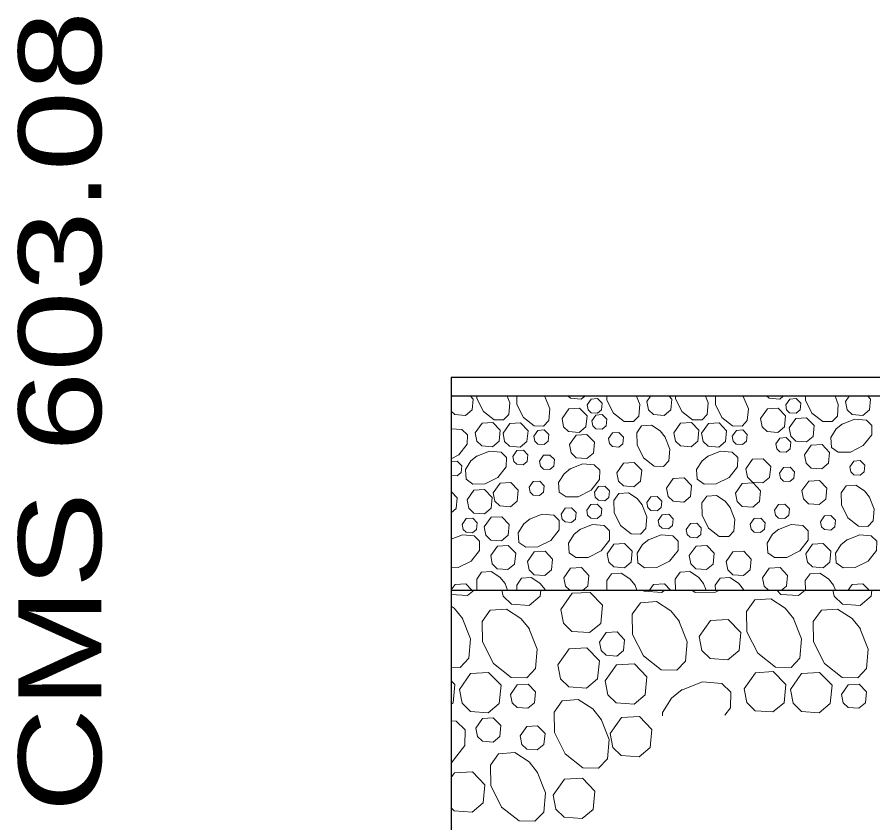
# Model space of a CAD drawing. Extents: x 1083.1 to 1117.1, y 697.4 to 741.4.
# Drawn here: x 1098.097 to 1099.707, y 705.8 to 707.316 of the extents above; entities that cross this region are included whole.
import ezdxf
from ezdxf.enums import TextEntityAlignment as Align

# ---------------------------------------------------------------- set-up
doc = ezdxf.new("R2010")
doc.units = 0
doc.header["$LTSCALE"] = 0.062
doc.layers.add('1', color=7, linetype='Continuous', lineweight=13)

msp = doc.modelspace()

# ---------------------------------------------------------------- linework, layer by layer
at = {"layer": '1', "lineweight": 25}
for p, q in [((1101.19942, 706.63767), (1098.91383, 706.63767)), ((1098.91383, 706.63767), (1098.91383, 705.41058)), ((1098.91383, 706.23775), (1101.19942, 706.23775))]:
    msp.add_line(p, q, dxfattribs=at)
at = {"layer": '1'}
for p, q in [((1098.91383, 706.60092), (1098.91525, 706.60292)), ((1099.08917, 706.60292), (1099.09025, 706.6015)), ((1099.28175, 706.593), (1099.28875, 706.60292)), ((1099.46275, 706.60292), (1099.46383, 706.6015)), ((1099.65533, 706.593), (1099.66233, 706.60292)), ((1099.01442, 706.2515), (1099.01983, 706.23775)), ((1099.25892, 706.24842), (1099.26317, 706.23775)), ((1099.38792, 706.2515), (1099.39342, 706.23775)), ((1099.6325, 706.24842), (1099.63675, 706.23775)), ((1099.08958, 706.24), (1099.09058, 706.23775)), ((1099.46317, 706.24), (1099.46417, 706.23775))]:
    msp.add_line(p, q, dxfattribs=at)
at = {"layer": '1', "lineweight": 25}
msp.add_lwpolyline([(1101.19942, 706.23775), (1101.19942, 706.63767), (1101.19942, 706.60292), (1098.91383, 706.60292)], dxfattribs=at)
at = {"layer": '1'}
for points in [[(1098.95008, 706.60292), (1098.95525, 706.5975), (1098.95317, 706.57708), (1098.94067, 706.56667), (1098.92067, 706.56808), (1098.91383, 706.57483)], [(1099.01883, 706.60292), (1099.02375, 706.59025), (1099.02192, 706.56842), (1099.01208, 706.55808), (1098.99433, 706.55833), (1098.97425, 706.57408), (1098.96208, 706.59842), (1098.962, 706.60292)], [(1099.08958, 706.60242), (1099.09908, 706.57875), (1099.09717, 706.55683), (1099.08733, 706.54658), (1099.06967, 706.54692), (1099.0495, 706.56258), (1099.03733, 706.58692), (1099.03708, 706.60292)], [(1099.16483, 706.60292), (1099.15825, 706.59742), (1099.13817, 706.59883), (1099.134, 706.60292)], [(1099.26217, 706.60292), (1099.26833, 706.58717), (1099.2665, 706.56533), (1099.25667, 706.555), (1099.23892, 706.55525), (1099.21875, 706.571), (1099.20667, 706.59533), (1099.2065, 706.60292)], [(1099.32367, 706.60292), (1099.32875, 706.5975), (1099.32683, 706.57708), (1099.31425, 706.56667), (1099.29425, 706.56808), (1099.28475, 706.57725), (1099.28183, 706.593)], [(1099.39233, 706.60292), (1099.39733, 706.59025), (1099.3955, 706.56842), (1099.38567, 706.55808), (1099.36792, 706.55833), (1099.34783, 706.57408), (1099.33567, 706.59842), (1099.33558, 706.60292)], [(1099.46317, 706.60242), (1099.47267, 706.57875), (1099.47075, 706.55683), (1099.46083, 706.54658), (1099.44317, 706.54692), (1099.42308, 706.56258), (1099.41092, 706.58692), (1099.41067, 706.60292)], [(1099.53842, 706.60292), (1099.53183, 706.59742), (1099.51175, 706.59883), (1099.50758, 706.60292)], [(1099.63575, 706.60292), (1099.64192, 706.58717), (1099.64008, 706.56533), (1099.63025, 706.555), (1099.6125, 706.55525), (1099.59233, 706.571), (1099.58025, 706.59533), (1099.58008, 706.60292)], [(1099.69725, 706.60292), (1099.70233, 706.5975), (1099.70033, 706.57708), (1099.68783, 706.56667), (1099.66783, 706.56808), (1099.65842, 706.57725), (1099.65533, 706.593)], [(1099.64917, 706.55008), (1099.67292, 706.5595), (1099.69467, 706.55767), (1099.70508, 706.54783), (1099.70467, 706.53008), (1099.68892, 706.51), (1099.66467, 706.49775), (1099.64175, 706.49733), (1099.62883, 706.50658), (1099.62758, 706.52483), (1099.63808, 706.54108), (1099.65008, 706.55075)], [(1098.91383, 706.54167), (1098.93367, 706.53992), (1098.94408, 706.53008), (1098.94375, 706.51242), (1098.928, 706.49225), (1098.91383, 706.48517)], [(1099.3155, 706.52675), (1099.325, 706.50308), (1099.32308, 706.48117), (1099.31325, 706.47083), (1099.29558, 706.47117), (1099.27542, 706.48692), (1099.26333, 706.51125), (1099.26292, 706.53417), (1099.272, 706.547), (1099.29025, 706.54833), (1099.30667, 706.53775), (1099.31617, 706.52575)], [(1098.96183, 706.49), (1098.98558, 706.49942), (1099.00742, 706.49758), (1099.01783, 706.48775), (1099.01742, 706.47), (1099.00167, 706.44992), (1098.97733, 706.43767), (1098.9545, 706.43725), (1098.94158, 706.4465), (1098.94033, 706.46475), (1098.95075, 706.481), (1098.96283, 706.49067)], [(1099.39683, 706.49), (1099.42058, 706.49942), (1099.44233, 706.49758), (1099.45275, 706.48775), (1099.45233, 706.47), (1099.43658, 706.44992), (1099.41233, 706.43767), (1099.38942, 706.43725), (1099.3765, 706.4465), (1099.37525, 706.46475), (1099.38575, 706.481), (1099.39775, 706.49067)], [(1098.91383, 706.47967), (1098.92508, 706.48033), (1098.9335, 706.47158), (1098.93225, 706.45933), (1098.92475, 706.453), (1098.91383, 706.45383)], [(1099.13725, 706.466), (1099.16108, 706.47542), (1099.18283, 706.4735), (1099.19325, 706.46367), (1099.19283, 706.446), (1099.17708, 706.42583), (1099.15275, 706.41367), (1099.12992, 706.41325), (1099.117, 706.4225), (1099.11575, 706.44075), (1099.12617, 706.457), (1099.13825, 706.46658)], [(1098.91383, 706.42367), (1098.92525, 706.41175), (1098.92325, 706.39125), (1098.91383, 706.38342)], [(1099.27225, 706.39942), (1099.28175, 706.37567), (1099.27983, 706.35383), (1099.27, 706.34342), (1099.25225, 706.34383), (1099.23217, 706.35958), (1099.22, 706.38392), (1099.21967, 706.40675), (1099.22875, 706.41967), (1099.247, 706.42092), (1099.26342, 706.41042), (1099.27292, 706.39842)], [(1099.7, 706.41383), (1099.70942, 706.39008), (1099.70758, 706.36825), (1099.69775, 706.35783), (1099.68, 706.35825), (1099.65992, 706.374), (1099.64775, 706.39833), (1099.64742, 706.42117), (1099.6565, 706.43408), (1099.67475, 706.43533), (1099.69117, 706.42483), (1099.70067, 706.41283)], [(1099.43808, 706.39458), (1099.4475, 706.37092), (1099.44567, 706.349), (1099.43583, 706.33867), (1099.41808, 706.339), (1099.398, 706.35475), (1099.38583, 706.37908), (1099.3855, 706.402), (1099.39458, 706.41483), (1099.41283, 706.41617), (1099.42917, 706.40558), (1099.43875, 706.39367)], [(1099.06125, 706.37142), (1099.085, 706.38083), (1099.10675, 706.37892), (1099.11708, 706.36908), (1099.11675, 706.35142), (1099.101, 706.33125), (1099.07675, 706.31917), (1099.05383, 706.31875), (1099.04092, 706.32783), (1099.03967, 706.34608), (1099.05017, 706.3625), (1099.06217, 706.372)], [(1099.15575, 706.35192), (1099.1795, 706.36133), (1099.20133, 706.3595), (1099.21175, 706.34958), (1099.21142, 706.33192), (1099.19567, 706.31183), (1099.17133, 706.29958), (1099.14842, 706.29925), (1099.1355, 706.30833), (1099.13433, 706.32658), (1099.14475, 706.343), (1099.15675, 706.35258)], [(1099.52933, 706.35192), (1099.55308, 706.36133), (1099.57492, 706.3595), (1099.58533, 706.34958), (1099.585, 706.33192), (1099.56925, 706.31183), (1099.54492, 706.29958), (1099.522, 706.29925), (1099.50908, 706.30833), (1099.50792, 706.32658), (1099.51833, 706.343), (1099.53033, 706.35258)], [(1098.91383, 706.33375), (1098.935, 706.34208), (1098.95675, 706.34025), (1098.96717, 706.33042), (1098.96683, 706.31267), (1098.95108, 706.29267), (1098.92675, 706.28042), (1098.91383, 706.28017)], [(1099.28475, 706.33275), (1099.30858, 706.34208), (1099.33033, 706.34025), (1099.34075, 706.33042), (1099.34042, 706.31267), (1099.32467, 706.29267), (1099.30025, 706.28042), (1099.27742, 706.28), (1099.2645, 706.28917), (1099.26333, 706.30742), (1099.27375, 706.32375), (1099.28575, 706.33342)], [(1099.65842, 706.33275), (1099.68217, 706.34208), (1099.70392, 706.34025), (1099.71433, 706.33042), (1099.71392, 706.31267), (1099.69817, 706.29267), (1099.67392, 706.28042), (1099.651, 706.28), (1099.63808, 706.28917), (1099.63692, 706.30742), (1099.64733, 706.32375), (1099.65933, 706.33342)], [(1099.20708, 706.3065), (1099.21983, 706.32458), (1099.24, 706.32567), (1099.25417, 706.31108), (1099.25217, 706.29058), (1099.23958, 706.28017), (1099.21958, 706.28167), (1099.21017, 706.29083), (1099.20717, 706.3065)], [(1099.12575, 706.26117), (1099.13842, 706.27925), (1099.15867, 706.28033), (1099.17275, 706.26583), (1099.17075, 706.24533), (1099.16158, 706.23775)], [(1099.49933, 706.26117), (1099.512, 706.27925), (1099.53225, 706.28033), (1099.54633, 706.26583), (1099.54433, 706.24533), (1099.53517, 706.23775)], [(1098.96208, 706.23775), (1098.96167, 706.25892), (1098.97083, 706.27175), (1098.98908, 706.273), (1099.00542, 706.2625), (1099.015, 706.2505)], [(1099.03708, 706.23775), (1099.03692, 706.24733), (1099.04608, 706.26025), (1099.06433, 706.2615), (1099.08067, 706.251), (1099.09025, 706.23908)], [(1099.13683, 706.23775), (1099.12883, 706.2455), (1099.12575, 706.26117)], [(1099.20658, 706.23775), (1099.20625, 706.25583), (1099.21542, 706.26875), (1099.23367, 706.26992), (1099.25, 706.25942), (1099.25958, 706.2475)], [(1099.33567, 706.23775), (1099.33525, 706.25892), (1099.34442, 706.27175), (1099.36267, 706.273), (1099.379, 706.2625), (1099.38858, 706.2505)], [(1099.41067, 706.23775), (1099.4105, 706.24733), (1099.41967, 706.26025), (1099.43792, 706.2615), (1099.45425, 706.251), (1099.46383, 706.23908)], [(1099.51042, 706.23775), (1099.50242, 706.2455), (1099.49933, 706.26117)], [(1099.58017, 706.23775), (1099.57983, 706.25583), (1099.589, 706.26875), (1099.60725, 706.26992), (1099.62358, 706.25942), (1099.63317, 706.2475)], [(1098.91383, 706.23842), (1098.92092, 706.2485), (1098.94108, 706.24967), (1098.95267, 706.23775)], [(1099.28683, 706.23775), (1099.2945, 706.2485), (1099.31467, 706.24967), (1099.32617, 706.23775)], [(1099.66042, 706.23775), (1099.66808, 706.2485), (1099.68825, 706.24967), (1099.69975, 706.23775)], [(1098.95667, 706.23775), (1098.94467, 706.22767), (1098.91383, 706.22992)], [(1099.08225, 706.23775), (1099.08108, 706.22667), (1099.06025, 706.20925), (1099.02692, 706.21167), (1099.01125, 706.22683), (1099.00917, 706.23775)], [(1099.31492, 706.23775), (1099.30992, 706.23358), (1099.2765, 706.236), (1099.27475, 706.23775)], [(1099.41858, 706.23775), (1099.41108, 706.23392), (1099.37292, 706.23333), (1099.36667, 706.23775)], [(1099.57933, 706.23775), (1099.56725, 706.22767), (1099.53392, 706.23008), (1099.526, 706.23775)], [(1099.70483, 706.23775), (1099.70375, 706.22667), (1099.68292, 706.20925), (1099.64958, 706.21167), (1099.63392, 706.22683), (1099.63175, 706.23775)], [(1099.34217, 706.18058), (1099.35783, 706.141), (1099.35467, 706.10467), (1099.33825, 706.08742), (1099.30875, 706.08792), (1099.27525, 706.11425), (1099.255, 706.15475), (1099.25425, 706.19292), (1099.26958, 706.21442), (1099.3, 706.21642), (1099.32717, 706.199), (1099.34317, 706.179)], [(1099.55717, 706.18575), (1099.57275, 706.14617), (1099.56967, 706.10983), (1099.55325, 706.0925), (1099.52375, 706.09308), (1099.49025, 706.11933), (1099.47, 706.15983), (1099.46925, 706.198), (1099.48458, 706.21958), (1099.515, 706.22158), (1099.54217, 706.20417), (1099.55817, 706.18417)], [(1098.91383, 706.20783), (1098.9195, 706.20417), (1098.9355, 706.18417)], [(1099.05992, 706.1665), (1099.07558, 706.12692), (1099.0725, 706.09058), (1099.056, 706.07333), (1099.0265, 706.07383), (1098.993, 706.10017), (1098.97283, 706.14067), (1098.97208, 706.17883), (1098.98733, 706.20033), (1099.01783, 706.20242), (1099.045, 706.18492), (1099.06092, 706.16492)], [(1099.6825, 706.1665), (1099.69825, 706.12692), (1099.69508, 706.09058), (1099.67867, 706.07333), (1099.64917, 706.07383), (1099.61567, 706.10017), (1099.59533, 706.14067), (1099.59475, 706.17883), (1099.61, 706.20033), (1099.64042, 706.20242), (1099.66767, 706.18492), (1099.68358, 706.16492)], [(1098.9345, 706.18575), (1098.95025, 706.14617), (1098.94708, 706.10983), (1098.93067, 706.0925), (1098.91383, 706.09283)], [(1099.46475, 706.05258), (1099.48592, 706.08267), (1099.51967, 706.08467), (1099.54317, 706.06025), (1099.53983, 706.02617), (1099.51892, 706.00883), (1099.48567, 706.01125), (1099.46992, 706.02642), (1099.46475, 706.0525)], [(1099.55175, 706.05125), (1099.57292, 706.08142), (1099.60675, 706.08325), (1099.63025, 706.059), (1099.62683, 706.02483), (1099.606, 706.0075), (1099.57267, 706.00992), (1099.55692, 706.02517), (1099.55183, 706.05125)], [(1098.91383, 706.06725), (1098.92058, 706.06025), (1098.91717, 706.02617), (1098.91383, 706.02333)], [(1099.31142, 706.00142), (1099.311, 706.00767), (1099.32842, 706.03492), (1099.34833, 706.05083)], [(1099.34675, 706.04983), (1099.38633, 706.0655), (1099.42267, 706.06233), (1099.44, 706.04592), (1099.43942, 706.01642), (1099.42875, 706.00275)], [(1099.19492, 705.99633), (1099.21067, 705.95683), (1099.2075, 705.92042), (1099.19108, 705.90317), (1099.16158, 705.90367), (1099.12808, 705.92992), (1099.10775, 705.97042), (1099.10717, 706.00867), (1099.12242, 706.03008), (1099.15283, 706.03217), (1099.18, 706.01467), (1099.196, 705.99475)], [(1098.91383, 705.99242), (1098.92283, 705.99167), (1098.94017, 705.97525), (1098.93958, 705.94575), (1098.91383, 705.91267)], [(1099.07525, 705.8965), (1099.09092, 705.857), (1099.08783, 705.82058), (1099.07133, 705.80333), (1099.04183, 705.80383), (1099.00833, 705.83008), (1098.98817, 705.87058), (1098.98742, 705.90883), (1099.00267, 705.93025), (1099.03317, 705.93233), (1099.06033, 705.91483), (1099.07625, 705.89492)], [(1098.91383, 705.88558), (1098.91992, 705.89433), (1098.95367, 705.89633), (1098.97717, 705.87192), (1098.97383, 705.83783), (1098.95292, 705.8205), (1098.9195, 705.82292), (1098.91383, 705.8285)]]:
    msp.add_lwpolyline(points, dxfattribs=at)
for points in [[(1099.16933, 706.58667), (1099.17692, 706.5975), (1099.18917, 706.59817), (1099.19758, 706.58942), (1099.19633, 706.57717), (1099.18883, 706.57083), (1099.17675, 706.57175), (1099.17117, 706.57725)], [(1099.54292, 706.58667), (1099.5505, 706.5975), (1099.56267, 706.59817), (1099.57117, 706.58942), (1099.56992, 706.57717), (1099.56242, 706.57083), (1099.55033, 706.57175), (1099.54475, 706.57725)], [(1099.12217, 706.561), (1099.13483, 706.579), (1099.15517, 706.58017), (1099.16925, 706.56558), (1099.16717, 706.54508), (1099.15467, 706.53467), (1099.13458, 706.53608), (1099.12525, 706.54525)], [(1099.17817, 706.55658), (1099.18583, 706.56733), (1099.19792, 706.56808), (1099.20642, 706.55933), (1099.20517, 706.54708), (1099.19767, 706.54075), (1099.18567, 706.54167), (1099.18, 706.54717)], [(1099.49575, 706.561), (1099.50842, 706.579), (1099.52867, 706.58017), (1099.54283, 706.56558), (1099.54075, 706.54508), (1099.52817, 706.53467), (1099.50817, 706.53608), (1099.49875, 706.54525)], [(1098.95892, 706.53408), (1098.97167, 706.55217), (1098.99192, 706.55333), (1099.006, 706.53867), (1099.00392, 706.51825), (1098.99142, 706.50775), (1098.9715, 706.50925), (1098.962, 706.51842)], [(1099.01117, 706.53325), (1099.02383, 706.55133), (1099.04417, 706.5525), (1099.05825, 706.53792), (1099.05617, 706.51742), (1099.04367, 706.50708), (1099.02367, 706.5085), (1099.01425, 706.51758)], [(1099.3325, 706.53408), (1099.34517, 706.55217), (1099.3655, 706.55333), (1099.37958, 706.53867), (1099.37758, 706.51825), (1099.365, 706.50775), (1099.34508, 706.50925), (1099.33558, 706.51842)], [(1099.38475, 706.53325), (1099.39742, 706.55133), (1099.41775, 706.5525), (1099.43183, 706.53792), (1099.42975, 706.51742), (1099.41725, 706.50708), (1099.39725, 706.5085), (1099.38783, 706.51758)], [(1099.54933, 706.543), (1099.56208, 706.56108), (1099.58233, 706.56225), (1099.59642, 706.54767), (1099.59433, 706.52717), (1099.58183, 706.51675), (1099.56183, 706.51817), (1099.55242, 706.52733)], [(1099.06892, 706.52775), (1099.07658, 706.5385), (1099.08875, 706.53925), (1099.09717, 706.5305), (1099.09592, 706.51825), (1099.08842, 706.51192), (1099.07642, 706.51283), (1099.07075, 706.51833)], [(1099.20942, 706.52292), (1099.21708, 706.53375), (1099.22917, 706.53442), (1099.23767, 706.52575), (1099.23642, 706.51342), (1099.22892, 706.50717), (1099.21692, 706.508), (1099.21125, 706.5135)], [(1099.4425, 706.52775), (1099.45017, 706.5385), (1099.46225, 706.53925), (1099.47075, 706.5305), (1099.4695, 706.51825), (1099.462, 706.51192), (1099.45, 706.51283), (1099.44433, 706.51833)], [(1099.13617, 706.51167), (1099.14883, 706.52975), (1099.16908, 706.53092), (1099.18317, 706.51625), (1099.18117, 706.49583), (1099.16867, 706.48542), (1099.14867, 706.48683), (1099.13925, 706.496)], [(1099.52425, 706.51333), (1099.53183, 706.52408), (1099.544, 706.52483), (1099.5525, 706.51608), (1099.55117, 706.50383), (1099.54375, 706.4975), (1099.53167, 706.49842), (1099.526, 706.50392)], [(1099.02967, 706.48958), (1099.03733, 706.5005), (1099.04942, 706.50117), (1099.05783, 706.49242), (1099.05667, 706.48008), (1099.04908, 706.47383), (1099.03717, 706.47475), (1099.0315, 706.48025)], [(1099.57833, 706.49242), (1099.591, 706.5105), (1099.61125, 706.51167), (1099.62533, 706.49708), (1099.62333, 706.47658), (1099.61083, 706.46625), (1099.59083, 706.46767), (1099.58142, 706.47675)], [(1099.07967, 706.48075), (1099.08725, 706.49158), (1099.09942, 706.49217), (1099.10783, 706.4835), (1099.10667, 706.47117), (1099.09917, 706.465), (1099.08708, 706.46583), (1099.0815, 706.47125)], [(1099.46775, 706.466), (1099.48042, 706.48408), (1099.50075, 706.48525), (1099.51483, 706.47067), (1099.51275, 706.45017), (1099.50025, 706.43975), (1099.48025, 706.44117), (1099.47083, 706.45033)], [(1099.22508, 706.45875), (1099.23775, 706.47683), (1099.258, 706.47808), (1099.27208, 706.46342), (1099.27008, 706.443), (1099.25758, 706.43258), (1099.23758, 706.434), (1099.22817, 706.44308)], [(1099.53142, 706.45808), (1099.53908, 706.46883), (1099.55117, 706.46958), (1099.55967, 706.46083), (1099.55842, 706.44858), (1099.55092, 706.44225), (1099.53892, 706.44308), (1099.53325, 706.44858)], [(1099.66358, 706.47008), (1099.67125, 706.48083), (1099.68333, 706.48158), (1099.69183, 706.47283), (1099.69058, 706.46058), (1099.68308, 706.45425), (1099.67108, 706.45517), (1099.66542, 706.46067)], [(1098.99292, 706.42108), (1099.00558, 706.43917), (1099.02592, 706.44025), (1099.04, 706.42575), (1099.03792, 706.40517), (1099.02542, 706.39483), (1099.00542, 706.39633), (1098.996, 706.40542)], [(1099.06042, 706.43167), (1099.06808, 706.44242), (1099.08017, 706.44308), (1099.08867, 706.43442), (1099.08742, 706.42208), (1099.07992, 706.41583), (1099.06792, 706.41667), (1099.06225, 706.42217)], [(1099.31875, 706.42992), (1099.33142, 706.448), (1099.35175, 706.44925), (1099.36583, 706.43458), (1099.36375, 706.41417), (1099.35125, 706.40375), (1099.33125, 706.40517), (1099.32183, 706.41425)], [(1099.4485, 706.42033), (1099.46117, 706.43842), (1099.4815, 706.43958), (1099.49558, 706.425), (1099.4935, 706.4045), (1099.481, 706.39417), (1099.46108, 706.39558), (1099.45158, 706.40467)], [(1099.5735, 706.42517), (1099.58617, 706.44325), (1099.6065, 706.44442), (1099.62058, 706.42975), (1099.6185, 706.40933), (1099.606, 706.39892), (1099.586, 706.40033), (1099.57658, 706.4095)], [(1098.94367, 706.40783), (1098.95642, 706.42592), (1098.97667, 706.42708), (1098.99075, 706.41242), (1098.98867, 706.392), (1098.97617, 706.38158), (1098.95617, 706.383), (1098.94675, 706.39217)], [(1099.183, 706.422), (1099.19058, 706.43283), (1099.20275, 706.4335), (1099.21125, 706.42475), (1099.21, 706.4125), (1099.2025, 706.40625), (1099.1905, 706.40708), (1099.18483, 706.41258)], [(1099.2815, 706.40283), (1099.28917, 706.41358), (1099.30125, 706.41425), (1099.30975, 706.40558), (1099.3085, 706.39325), (1099.301, 706.387), (1099.289, 706.38783), (1099.28333, 706.39333)], [(1099.1205, 706.38117), (1099.12817, 706.39192), (1099.14025, 706.39267), (1099.14875, 706.38392), (1099.1475, 706.37167), (1099.14, 706.36533), (1099.128, 706.36625), (1099.12233, 706.37175)], [(1099.16858, 706.38842), (1099.17617, 706.39917), (1099.18833, 706.39992), (1099.19683, 706.39117), (1099.19558, 706.37883), (1099.18808, 706.37258), (1099.17608, 706.37342), (1099.17033, 706.37892)], [(1099.52183, 706.38842), (1099.52942, 706.39917), (1099.54158, 706.39992), (1099.55008, 706.39117), (1099.54883, 706.37883), (1099.54133, 706.37258), (1099.52925, 706.37342), (1099.52367, 706.37892)], [(1098.93442, 706.36167), (1098.942, 706.3725), (1098.95425, 706.37317), (1098.96267, 706.36442), (1098.96142, 706.35217), (1098.95392, 706.34592), (1098.94192, 706.34675), (1098.93633, 706.35225)], [(1098.976, 706.357), (1098.98867, 706.37508), (1099.009, 706.37617), (1099.02308, 706.36158), (1099.021, 706.34117), (1099.0085, 706.33067), (1098.9885, 706.33217), (1098.97908, 706.34133)], [(1099.30317, 706.36917), (1099.31075, 706.37992), (1099.32292, 706.38067), (1099.33142, 706.37192), (1099.33017, 706.35967), (1099.32267, 706.35333), (1099.31058, 706.35425), (1099.30492, 706.35975)], [(1099.47617, 706.362), (1099.48383, 706.37275), (1099.49592, 706.37342), (1099.50442, 706.36475), (1099.50317, 706.35242), (1099.49567, 706.34617), (1099.48367, 706.347), (1099.478, 706.3525)], [(1099.60833, 706.36675), (1099.61592, 706.3775), (1099.62808, 706.37825), (1099.63658, 706.3695), (1099.63533, 706.35725), (1099.62783, 706.35092), (1099.61583, 706.35183), (1099.61017, 706.35733)], [(1099.356, 706.35233), (1099.36367, 706.36308), (1099.37575, 706.36383), (1099.38425, 706.35508), (1099.383, 706.34283), (1099.3755, 706.3365), (1099.3635, 706.33742), (1099.35783, 706.34292)], [(1099.58067, 706.3065), (1099.59342, 706.32458), (1099.61358, 706.32567), (1099.62767, 706.31108), (1099.62567, 706.29058), (1099.61317, 706.28017), (1099.59317, 706.28167), (1099.58375, 706.29083)], [(1098.988, 706.30292), (1099.00067, 706.321), (1099.02092, 706.32217), (1099.035, 706.30758), (1099.033, 706.287), (1099.0205, 706.27667), (1099.00042, 706.27808), (1098.99108, 706.28717)], [(1099.05733, 706.29183), (1099.07, 706.30992), (1099.09033, 706.31108), (1099.10442, 706.2965), (1099.10233, 706.276), (1099.08983, 706.26558), (1099.06983, 706.26708), (1099.06042, 706.27617)], [(1099.36158, 706.30292), (1099.37425, 706.321), (1099.3945, 706.32217), (1099.40858, 706.30758), (1099.40658, 706.287), (1099.39408, 706.27667), (1099.374, 706.27808), (1099.36467, 706.28717)], [(1099.43092, 706.29183), (1099.44358, 706.30992), (1099.46392, 706.31108), (1099.478, 706.2965), (1099.47592, 706.276), (1099.46342, 706.26558), (1099.44342, 706.26708), (1099.434, 706.27617)], [(1099.12008, 706.20183), (1099.14125, 706.232), (1099.175, 706.23383), (1099.1985, 706.20958), (1099.19508, 706.17542), (1099.17417, 706.15808), (1099.14083, 706.1605), (1099.12517, 706.17575)], [(1099.38017, 706.15075), (1099.40133, 706.18075), (1099.435, 706.18275), (1099.45858, 706.15833), (1099.45517, 706.12425), (1099.43425, 706.10692), (1099.40092, 706.10933), (1099.38525, 706.1245)], [(1099.19275, 706.14017), (1099.20542, 706.15825), (1099.22575, 706.15942), (1099.23983, 706.14483), (1099.23775, 706.12433), (1099.22525, 706.11392), (1099.20525, 706.11542), (1099.19583, 706.1245)], [(1099.11417, 706.09742), (1099.13533, 706.12742), (1099.16908, 706.12942), (1099.1925, 706.10508), (1099.18917, 706.07092), (1099.16825, 706.05358), (1099.13492, 706.056), (1099.11925, 706.07117)], [(1099.2035, 706.0675), (1099.22467, 706.09758), (1099.25842, 706.0995), (1099.282, 706.07517), (1099.27858, 706.04108), (1099.25767, 706.02367), (1099.22433, 706.02608), (1099.20867, 706.04133)], [(1098.92925, 706.05125), (1098.95033, 706.08142), (1098.98417, 706.08325), (1099.00758, 706.059), (1099.00417, 706.02483), (1098.98333, 706.0075), (1098.95, 706.00992), (1098.93433, 706.02517)], [(1099.02542, 706.042), (1099.03808, 706.06008), (1099.05842, 706.06117), (1099.0725, 706.04667), (1099.07042, 706.02617), (1099.05792, 706.01575), (1099.03792, 706.01725), (1099.0285, 706.02633)], [(1099.64808, 706.042), (1099.66075, 706.06008), (1099.681, 706.06117), (1099.69508, 706.04667), (1099.69308, 706.02617), (1099.68058, 706.01575), (1099.66058, 706.01725), (1099.65117, 706.02633)], [(1098.96, 705.9785), (1098.97267, 705.99658), (1098.99292, 705.99767), (1099.007, 705.98317), (1099.005, 705.96258), (1098.9925, 705.95225), (1098.97242, 705.95375), (1098.963, 705.96283)], [(1099.213, 705.9685), (1099.23417, 705.99858), (1099.26783, 706.0005), (1099.29133, 705.97617), (1099.28792, 705.94208), (1099.26708, 705.92467), (1099.23375, 705.92717), (1099.21808, 705.94233)], [(1099.04325, 705.96367), (1099.05592, 705.98167), (1099.07625, 705.98283), (1099.09033, 705.96817), (1099.08825, 705.94775), (1099.07575, 705.93733), (1099.05583, 705.93875), (1099.04633, 705.94792)], [(1099.10575, 705.85208), (1099.12692, 705.88225), (1099.16067, 705.88408), (1099.18417, 705.85983), (1099.18075, 705.82567), (1099.15983, 705.80833), (1099.1265, 705.81075), (1099.11083, 705.826)]]:
    msp.add_lwpolyline(points, close=True, dxfattribs=at)

# ---------------------------------------------------------------- texts
at = {"layer": '1', "width": 1.3}
msp.add_text('CMS 603.08', height=0.156, rotation=90, dxfattribs=at).set_placement((1098.2555, 706.57383), align=Align.CENTER)

doc.saveas('drawing.dxf')
